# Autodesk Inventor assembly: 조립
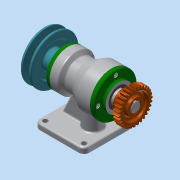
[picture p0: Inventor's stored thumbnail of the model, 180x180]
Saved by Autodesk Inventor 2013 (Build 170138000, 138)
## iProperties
Created: 2019-01
Part Number: 조립
Document SubType Name: Assembly
Designer: Administrator
Author: Administrator
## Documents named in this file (15)
- C:\Users\Administrator\Desktop\Manufacturing_20180922\조립.iam
- C:\Users\Administrator\Desktop\Manufacturing_20180922\본체.ipt
- C:\Users\Administrator\Desktop\Manufacturing_20180922\490107V1021\뒤커버.ipt
- C:\Users\Administrator\Desktop\Manufacturing_20180922\490107V1021\앞커버.ipt
- C:\Users\Administrator\Desktop\Manufacturing_20180922\490107V1021\축.ipt
- C:\Users\Administrator\Desktop\Manufacturing_20180922\490107V1021\베어링 6203.ipt
- C:\Users\Administrator\Desktop\Manufacturing_20180922\490107V1021\베어링 6205.ipt
- C:\Users\Administrator\Desktop\Manufacturing_20180922\490107V1021\오일 실 17 30 8.ipt
- C:\Users\Administrator\Desktop\Manufacturing_20180922\490107V1021\오일 실 25 38 8.ipt
- C:\Users\Administrator\Desktop\Manufacturing_20180922\490107V1021\키 5 x 5 x 20.ipt
- C:\Users\Administrator\Desktop\Manufacturing_20180922\490107V1021\키 6 x 6 x 18.ipt
- C:\Users\Administrator\Desktop\Manufacturing_20180922\490107V1021\스퍼기어.ipt
- C:\Users\Administrator\Desktop\Manufacturing_20180922\490107V1021\멈춤나사 M3.ipt
- C:\Users\Administrator\Desktop\Manufacturing_20180922\490107V1021\V-벨트풀리.ipt
- C:\Users\Administrator\Desktop\Manufacturing_20180922\490107V1021\볼트 M4.ipt
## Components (1 placed, 1 different names)
1. V-벨트풀리:1 — 각도:2
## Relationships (1: Angle 1)
- 각도:2 [Angle]: V-벨트풀리:1
